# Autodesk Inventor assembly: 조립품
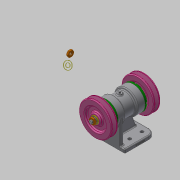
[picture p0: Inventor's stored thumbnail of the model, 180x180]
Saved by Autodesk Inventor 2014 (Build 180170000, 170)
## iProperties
Created: 2020-06
Part Number: 조립품
Document SubType Name: Assembly
Designer: kh
Author: kh
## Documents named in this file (11)
- C:\Users\kh\Desktop\700606V1025\조립품.iam
- C:\Users\kh\Desktop\700606V1025\본체.ipt
- C:\Users\kh\Desktop\700606V1025\베어링 6204.ipt
- C:\Users\kh\Desktop\700606V1025\축.ipt
- C:\Users\kh\Desktop\700606V1025\커버.ipt
- C:\Users\kh\Desktop\700606V1025\오일 실 20 32 5.ipt
- C:\Users\kh\Desktop\700606V1025\Ű 5x5x12.ipt
- C:\Users\kh\Desktop\700606V1025\V-벨트풀리.ipt
- C:\Users\kh\Desktop\700606V1025\평면 와셔 10x21.ipt
- C:\Users\kh\Desktop\700606V1025\스프링 와셔 10.ipt
- C:\Users\kh\Desktop\700606V1025\너트 M10.ipt
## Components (4 placed, 2 different names)
1. Ű 5x5x12:1 — Mate:17, Mate:18, Mate:19, Mate:24
2. Ű 5x5x12:2 — Mate:14, Mate:15, Mate:16, Mate:22
3. V-벨트풀리:1 — Mate:20, Mate:22, Mate:23, Mate:28
4. V-벨트풀리:2 — Mate:21, Mate:24, Mate:25, Mate:30
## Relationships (14: Mate 14)
- Mate:14: Ű 5x5x12:2
- Mate:15: Ű 5x5x12:2
- Mate:16: Ű 5x5x12:2
- Mate:17: Ű 5x5x12:1
- Mate:18: Ű 5x5x12:1
- Mate:19: Ű 5x5x12:1
- Mate:20: V-벨트풀리:1
- Mate:21: V-벨트풀리:2
- Mate:22: Ű 5x5x12:2 ↔ V-벨트풀리:1
- Mate:23: V-벨트풀리:1
- Mate:24: Ű 5x5x12:1 ↔ V-벨트풀리:2
- Mate:25: V-벨트풀리:2
- Mate:28: V-벨트풀리:1
- Mate:30: V-벨트풀리:2
